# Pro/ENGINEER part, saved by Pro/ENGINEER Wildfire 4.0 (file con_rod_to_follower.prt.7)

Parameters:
  METRIC = "NO"

Other parameters: PITCH, DRILL_POINT_ANGLE, DRILL_DEPTH, DRILL_DIAMETER, THREAD_DIAMETER, THREADS_PER_INCH, THREAD_DEPTH, THREAD_LENGTH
